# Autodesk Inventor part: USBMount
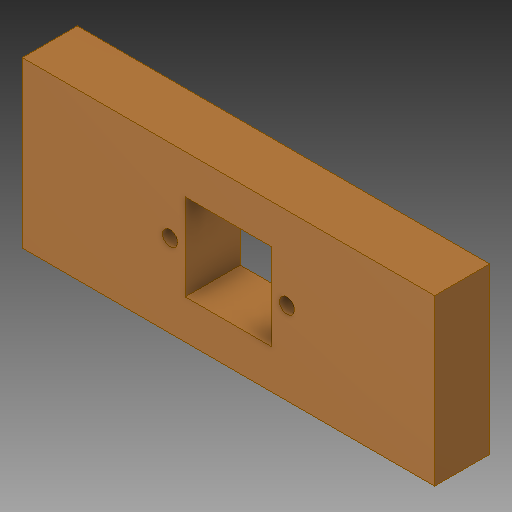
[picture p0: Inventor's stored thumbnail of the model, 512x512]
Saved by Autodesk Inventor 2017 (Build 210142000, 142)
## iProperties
Created: 2017-05
Part Number: USBMount
Material: Generic
Document SubType Name: Modeling
Designer: Savy
Density: 1 g/cm^3
Appearance: Default
Mass: 40.7642 g
Surface Area: 111.019 cm^2
Volume: 40.7642 cm^3
Author: Savy
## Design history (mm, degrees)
feature "SOLID1"
body "Solid1"
